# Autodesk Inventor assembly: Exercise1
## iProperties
Shininess: 0.0
Length Units: 11269
Angle Units: 11279
Time Units: 11290
Mass Units: 11283
Length Display Precision: 3
Angle Display Precision: 2
Created: 2000-11
Part Number: Exercise1
Description: Protective arch with side covers
Document SubType Name: Assembly
Designer: Joe M
Engineer: Joe M
Density: 0.0
Volumn: 0.0
Area: 0.0
PropertySet Name: Model Information
Control State: 0
Master: False
Checked Out: False
Title: Störtbåge med sidoplåtar
Author: Joe M
